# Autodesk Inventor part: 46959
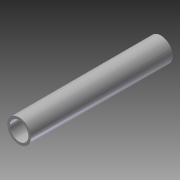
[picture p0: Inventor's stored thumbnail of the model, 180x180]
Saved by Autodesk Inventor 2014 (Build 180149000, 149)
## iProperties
Shininess: 64.0
Length Units: 11272
Angle Units: 11279
Time Units: 11290
Mass Units: 11286
Length Display Precision: 3
Angle Display Precision: 2
Company: Autodesk, Inc.
Created: 2002-06
Part Number: 46959
Material: Stainless Steel, Austenitic
Description: Spacer; .63 X .065WL X 3.75 (SS)
Document SubType Name: Modeling
Designer: Autodesk, Inc.
Density: 8.03 g/cm^3
Mass: 56.4286 g
Surface Area: 86.6024 cm^2
Volume: 7.02722 cm^3
Appearance: Steel
Density: 0.0
Volumn: 0.0
Area: 0.0
PropertySet Name: Model Information
Control State: 0
Master: False
Checked Out: False
Last Check In By: JT
Last Check In Date: 2003-06-20
Title: Spacer
Author: Autodesk, Inc.
Revision Number: -
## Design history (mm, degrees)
sketch "Sketch1"
  geometry: C1 r 7.938 at (0, 0); C2 r 6.287 at (0, 0); 1 further point
  constraints: 2 centre point, 2 coincident
  dimensions: "d0" = 15.875 diameter of C1; "d1" = 1.651 radial gap between concentric circles of C1 C2
extrude "Extrusion1" new body sketch "Sketch1" stored distance "d2" = 95.25; taper "d3" = 0 deg
body "Solid1"
